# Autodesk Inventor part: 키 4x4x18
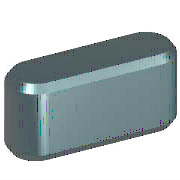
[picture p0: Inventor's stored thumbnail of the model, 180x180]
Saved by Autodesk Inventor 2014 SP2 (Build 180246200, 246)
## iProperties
IsCustomPart: 1
Created: 2012-02
Part Number: 키 4x4x18
Material: 강철, 연강
Description: 키 및 해당 키홈
Document SubType Name: Modeling
Standard: KS B 1311
Designer: mduedu
Standards Organization: KS
Language: ko-KR
Size Designation: 4 x 4 x 18
Categories: <MemberInstance><Categories><Category DisplayName="샤프트 부품" InternalName="7f7aeb1f-a693-4053-b835-cee3144e0d98" Mnemonic="SHFT"><Category DisplayName="키" Interna
Density: 7.86 g/cm^3
Mass: 2.13606 g
Surface Area: 2.87354 cm^2
Volume: 0.271763 cm^3
Appearance: 노란색
Author: mduedu
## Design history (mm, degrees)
workplane "Work Plane1"
workplane "Work Plane2"
sketch "스케치1"
  geometry: L1 (2, 2)-(16, 2); L2 (16, -2)-(2, -2); L3 (0, 9.4)-(0, -7.4) reference; L4 (-5, 0)-(30, 0) reference; L5 (18, 0)-(18, 7); A1 r 2 centre (2, 0) between (2, 2) and (2, -2); A2 r 2 centre (16, 0) between (16, -2) and (16, 2)
  constraints: 6 end point, 5 point on circle, 4 tangent, 3 point on line, 2 centre point, 1 horizontal, 1 parallel, 1 perpendicular
  dimensions: "d0" = 2 radius of A1 (= 0.5 x PB); "d13" = 2 radius of A2 (= 0.5 x PB); "d14" = 18 distance between parallel lines of L5 L3 (= NLG)
extrude "본체1" new body sketch "스케치1" taper "d3" = 0 deg; stored distance "d4" = 10
workplane "Work Plane3"
body "Solid1"
chamfer "모따기1" distance "d8" = 0.25 (= PHH); stored, may be unused: second distance "d9" = 0.25 (= PHH), angle "d15" = 45 deg
other parameters: "d1" = -2.5 (= -PNT), "d2" = 1.5 (= PH - PNT), "NLG" = 18 [user parameter; used in 3 equation terms], "PB" = 4 [user parameter; used in 2 equation terms], "PNT" = 2.5 [user parameter; used in 2 equation terms], "PH" = 4 [user parameter; used in 1 equation term], "PHH" = 0.25 [user parameter; used in 2 equation terms], "d10" = 0, "d16" = 0, "d17" = 0, "d18" = 0, "PLB2" = 18 (= NLG) [user parameter], "WDMAX" = 12 [user parameter], "PLB1" = 18 (= NLG) [user parameter], "RR" = 0.08 [user parameter], "PUEB" = 1.8 [user parameter]
